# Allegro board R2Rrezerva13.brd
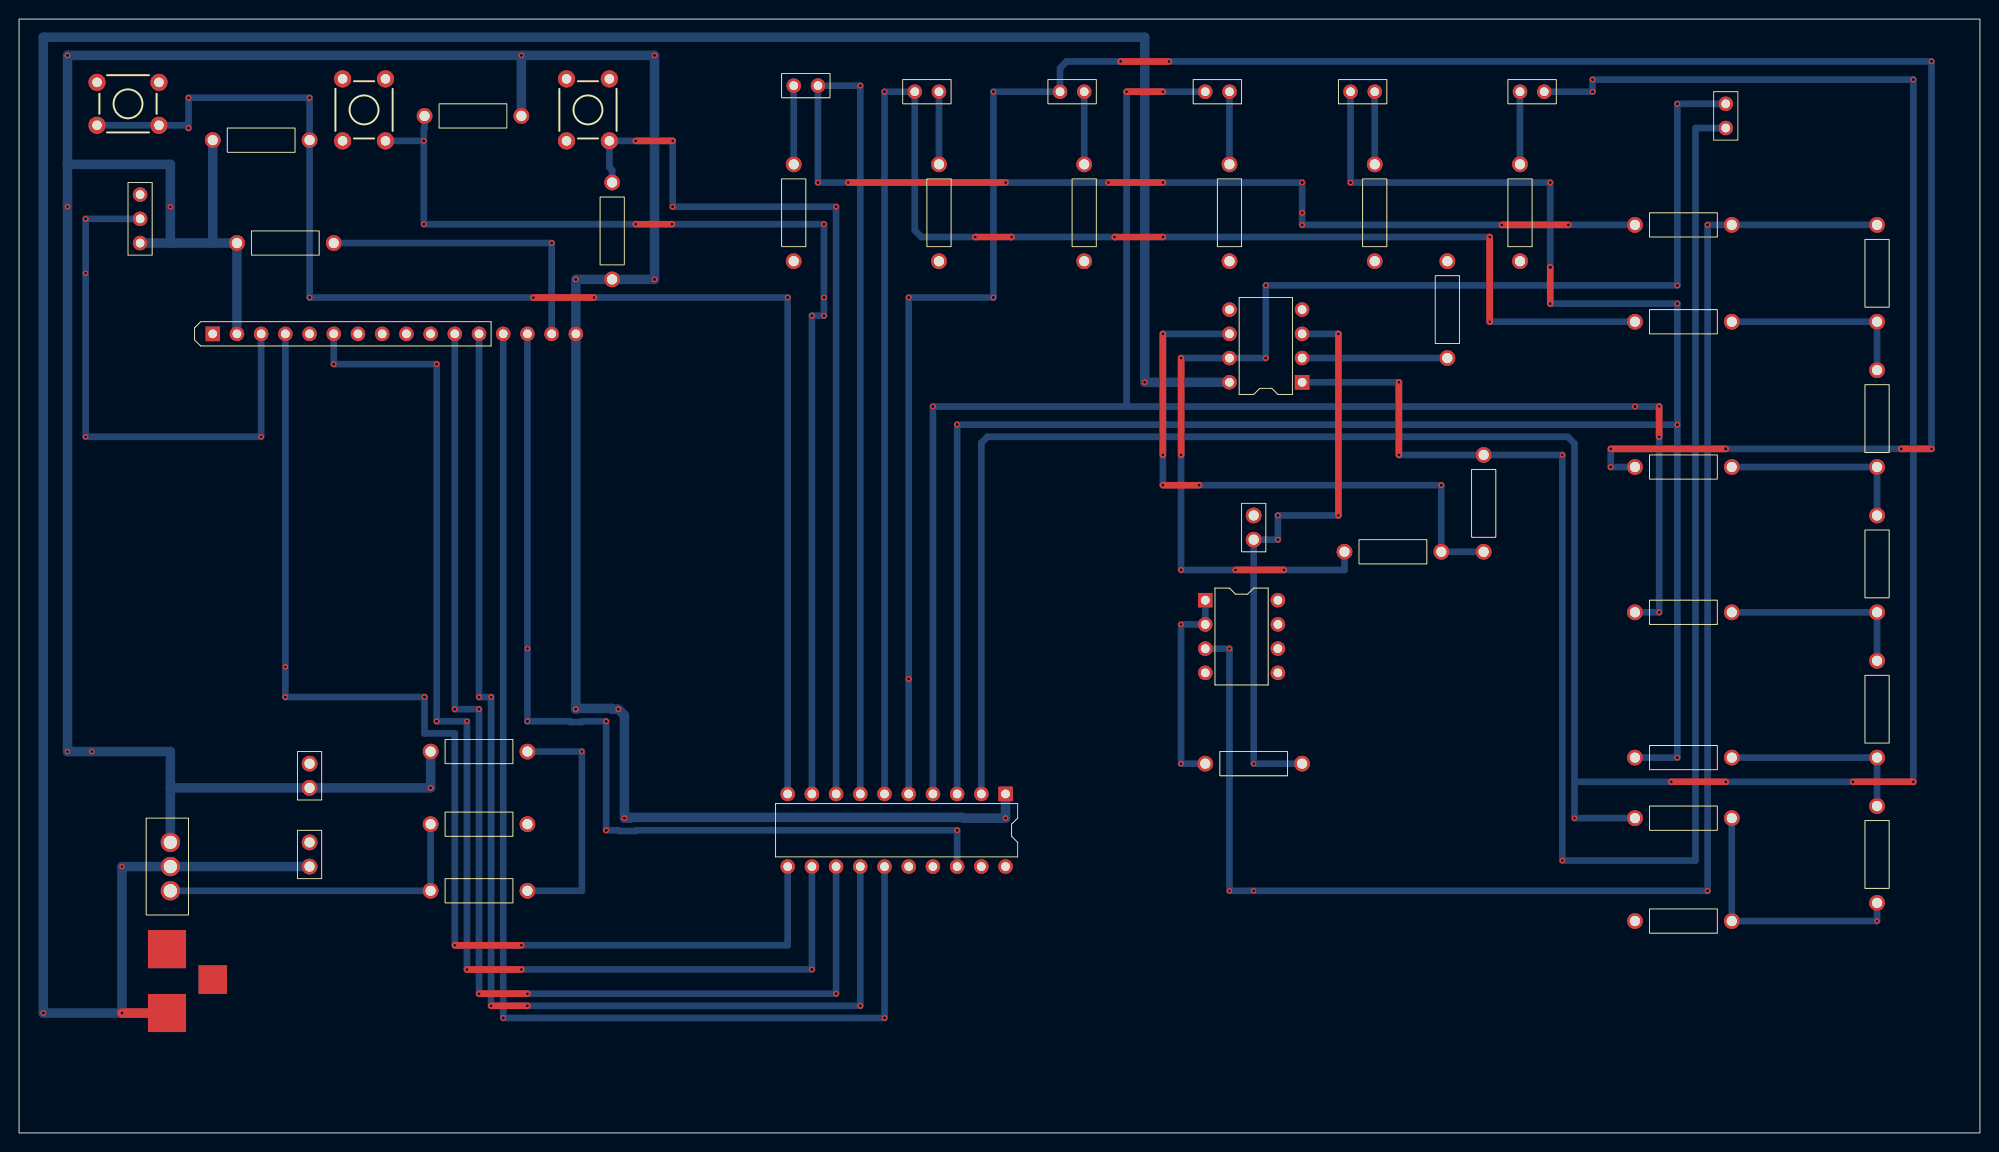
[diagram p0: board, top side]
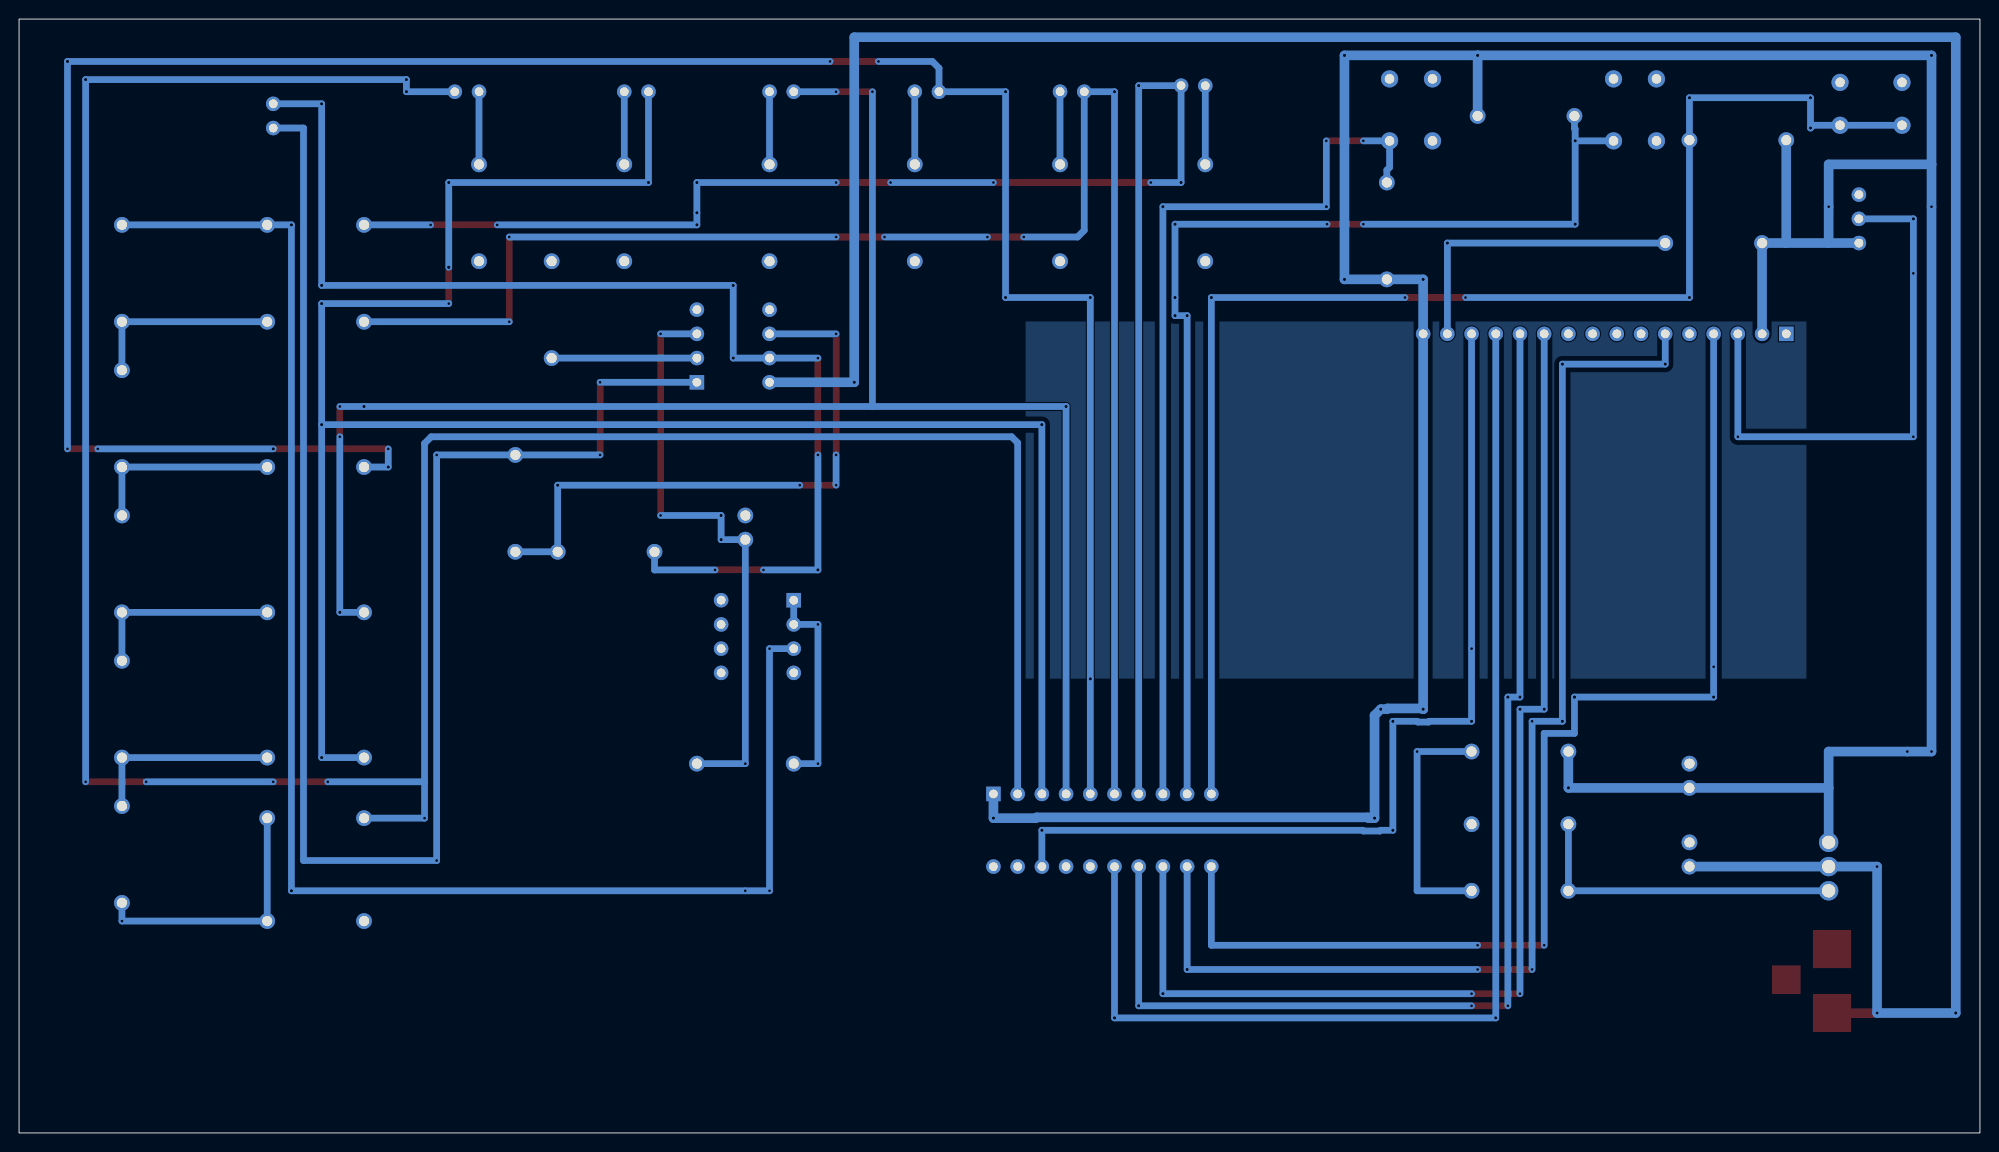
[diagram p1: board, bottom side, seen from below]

Outline 205.74 x 116.84 mm; copper layers: TOP, BOTTOM. Coordinates in mm from the lower left corner of the outline.
Outline path: rectangle 0,0 205.74,116.84

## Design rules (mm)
nets with their own width: min track width 0.7; nets N00328 N00336 N00340 N00355 N00395 N00470 N01662 N01669 N01683 N01690 N01717 N006340 N006500 N006660 N006820 N006980 N007140 N20855 N23488 N23661 N24189 N24193 N25824 N25853 N29134 N35057 N35516 N35592 N35638 N35656 N35674 N35692 N35721 N209781 SW1 SW2 SW3
nets with their own width: min track width 1; nets 0 9V V+ V- VCC

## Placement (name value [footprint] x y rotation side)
C3  10nf  [CAPCK05]  129.54 62.23 0 top
C4  10u  [CAPCK05]  30.48 30.48 180 top
C5  10u  [CAPCK05]  30.48 38.73 180 top
D1  MLED81  [JUMPER2]  83.82 109.85 180 top
D2  MLED81  [JUMPER2]  93.98 109.22 0 top
D3  MLED81  [JUMPER2]  109.22 109.22 0 top
D4  MLED81  [JUMPER2]  124.46 109.22 0 top
D5  MLED81  [JUMPER2]  139.7 109.22 0 top
D6  MLED81  [JUMPER2]  160.02 109.22 180 top
J1  Speaker  [JUMPER2]  179.07 105.41 90 top
J2  LCD 1602  [SIP16]  20.32 83.82 90 top
J3  CON3  [JACK_DC]  20.32 5.08 90 top
R2  1k  [RES400]  194.94 85.09 0 top
R3  1k  [RES400]  194.94 69.85 0 top
R4  1k  [RES400]  194.94 54.61 0 top
R5  1k  [RES400]  194.94 39.37 0 top
R6  1k  [RES400]  194.94 24.13 0 top
R7  2k  [RES400]  169.55 33.02 270 top
R8  2k  [RES400]  169.55 39.37 270 top
R9  2k  [RES400]  169.55 54.61 270 top
R10  2k  [RES400]  169.55 69.85 270 top
R11  2k  [RES400]  169.55 85.09 270 top
R12  2k  [RES400]  169.55 95.25 270 top
R13  2k  [RES400]  169.55 22.22 270 top
R14  470  [RES400]  157.48 91.44 0 top
R15  470  [RES400]  142.24 91.44 0 top
R16  470  [RES400]  127 91.44 0 top
R17  470  [RES400]  111.76 91.44 0 top
R18  470  [RES400]  96.52 91.44 0 top
R19  470  [RES400]  81.28 91.44 0 top
R20  10k  [RES400]  149.86 81.28 0 top
R22  10k  [RES400]  153.67 60.96 0 top
R23  1k  [RES400]  53.34 32.38 90 top
R24  470  [RES400]  53.34 40 90 top
R25  150  [RES400]  43.18 25.4 270 top
R26  33k  [RES400]  124.46 38.73 270 top
R28  10k  [RES400]  139.06 60.96 270 top
R29  1k  [JUMPER3]  12.7 98.42 270 top
R30  10k  [RES400]  30.48 104.14 90 top
R33  1k  [RES400]  22.86 93.34 270 top
R34  10k  [RES400]  42.55 106.68 270 top
R35  10k  [RES400]  62.23 99.69 180 top
SW7  SW_TC_SPST  [SW_SCHURTER_13019306L]  11.43 107.95 90 top
SW8  SW_TC_SPST  [SW_SCHURTER_13019306L]  36.19 107.31 180 top
SW9  SW_TC_SPST  [SW_SCHURTER_13019306L]  59.69 107.31 180 top
U1  MSP430G2553  [DIP20]  103.5 35.56 270 top
U7  LM317K  [TO220AB]  15.88 25.4 270 top
U9  LM358  [DIP8_3]  134.62 78.74 180 top
U10  LM358  [DIP8_3]  124.46 55.88 0 top

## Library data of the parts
C3-C5 = C: Tolerance: ***; User Part Number: ***
D1-D6 = MLED81: User Part Number: ***
J1 = CON2: User Part Number: ***
J2 = CON16: User Part Number: ***
J3 = CON3
R2-R20 R22-R26 R28 R30 R33-R35 = R: Tolerance: ***; User Part Number: ***
R29 = POT: User Part Number: ***
SW7-SW9 = SW_TC_SPST
U1 = MSP430G2553_4: Tolerance: ***; User Part Number: ***
U7 = LM317T
U9 = LM358: Tolerance: ***; User Part Number: ***
U10 = LM358_0: Tolerance: ***; User Part Number: ***

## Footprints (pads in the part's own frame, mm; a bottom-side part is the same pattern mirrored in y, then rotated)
CAPCK05
  round 1.651 hole 1.067: 1(0,0) 2(0,2.54)
DIP8_3
  rect 1.524x1.524 hole 0.914: 1(0,0)
  round 1.524 hole 0.914: 2(0,-2.54) 3(0,-5.08) 4(0,-7.62) 5(7.62,-7.62) 6(7.62,-5.08) 7(7.62,-2.54) 8(7.62,0)
DIP20
  rect 1.524x1.524 hole 0.914: 1(0,0)
  round 1.524 hole 0.914: 2(0,-2.54) 3(0,-5.08) 4(0,-7.62) 5(0,-10.16) 6(0,-12.7) 7(0,-15.24) 8(0,-17.78) 9(0,-20.32) 10(0,-22.86) 11(7.62,-22.86) 12(7.62,-20.32) 13(7.62,-17.78) 14(7.62,-15.24) 15(7.62,-12.7) 16(7.62,-10.16) 17(7.62,-7.62) 18(7.62,-5.08) 19(7.62,-2.54) 20(7.62,0)
JACK_DC
  rect 4x4 smd: 1(7.5,4.8) 2(14.2,4.8)
  rect 3x3 smd: 3(11,0)
JUMPER2
  round 1.524 hole 0.914: 1(0,0) 2(2.54,0)
JUMPER3
  round 1.524 hole 0.914: 1(0,0) 2(2.54,0) 3(5.08,0)
RES400
  round 1.651 hole 1.067: 1(0,0) 2(0,10.16)
SIP16
  rect 1.524x1.524 hole 0.914: 1(0,0)
  round 1.524 hole 0.914: 2(0,-2.54) 3(0,-5.08) 4(0,-7.62) 5(0,-10.16) 6(0,-12.7) 7(0,-15.24) 8(0,-17.78) 9(0,-20.32) 10(0,-22.86) 11(0,-25.4) 12(0,-27.94) 13(0,-30.48) 14(0,-33.02) 15(0,-35.56) 16(0,-38.1)
SW_SCHURTER_13019306L
  round 1.8 hole 1: 1(-2.25,-3.25) 2(-2.25,3.25) 3(2.25,3.25) 4(2.25,-3.25)
TO220AB
  round 2.032 hole 1.397: 1(0,0) 2(-2.54,0) 3(-5.08,0)

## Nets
9V: C4.2 J3.1 U7.2(IN) U9.8(V+)
VCC: C5.2 J2.2 J2.16 R24.2 R29.3(2) R30.2 R33.1 R34.2 R35.2 U1.1(DVCC) U7.3(OUT)
0: C3.2 C4.1 C5.1 J2.1 J2.5 J3.2 J3.3 R13.1 R14.1 R15.1 R16.1 R17.1 R18.1 R19.1 R20.2 R23.1 R29.1 SW7.3 SW8.3 SW9.3 U1.20(GROUND) U9.4(V-) U9.5(+)
SW1: R30.1 SW7.1 SW7.2 U1.10(P2_2)
SW2: R34.1 SW8.1 SW8.2 U1.9(P2_1)
SW3: R35.1 SW9.1 SW9.2 U1.8(P2_0/CS(B0))
V+: U10.8(V+)
V-: U10.4(V-)
N00328: R2.1 R3.2 R11.2
N00336: R4.1 R5.2 R9.2
N00340: R5.1 R6.2 R8.2
N00355: R2.2 R12.2 U10.3(+)
N00395: R3.1 R4.2 R10.2
N00470: R6.1 R7.2 R13.2
N01662: D5.1(A) R8.1 U1.3(P1_1/A1/RXD)
N01669: D4.1(A) R9.1 U1.4(P1_2/A2/TXD)
N01683: D2.1(A) R11.1 U1.6(P1_4/A4)
N01690: D1.1(A) R12.1 U1.7(P1_5/A5/SCK(B0))
N01717: D3.1(A) R10.1 U1.5(P1_3/A3/PUSH2)
N006340: D6.2(C) R14.2
N006500: D5.2(C) R15.2
N006660: D4.2(C) R16.2
N006820: D3.2(C) R17.2
N006980: D2.2(C) R18.2
N007140: D1.2(C) R19.2
N20855: R23.2 R25.1 U7.1(ADJ)
N23488: C3.1 R26.2 U9.3(+)
N23661: R26.1 U10.1(OUT) U10.2(-)
N24189: R20.1 U9.2(-)
N24193: J1.1 R22.2 U9.1(OUT)
N25824: R22.1 R28.2 U9.6(-)
N25853: J1.2 R28.1 U9.7(OUT)
N29134: D6.1(A) R7.1 U1.2(P1_0/A0/RED_LED)
N35057: J2.3 R29.2(T)
N35516: J2.4 U1.11(P2_3)
N35592: J2.6 U1.12(P2_4)
N35638: J2.11 U1.13(P2_5)
N35656: J2.12 U1.14(P1_6/A6/SCL/MISO(B0)/GREEN LED)
N35674: J2.13 U1.15(P1_7/A7/SDA/MOSE(B0))
N35692: J2.14 U1.18(P2_7/XOUT)
N35721: J2.15 R33.2
N209781: R24.1 R25.2

Pads without a net: J2 7 8 9 10; SW7 4; SW8 4; SW9 4; U1 16 17 19; U10 5 6 7

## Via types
v1: diameter 0.6, hole 0.3, TOP to BOTTOM, 240 vias

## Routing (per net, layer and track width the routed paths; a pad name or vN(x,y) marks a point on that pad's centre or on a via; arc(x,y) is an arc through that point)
9V: length 311
  TOP w1: J3.1 v1(10.8,12.58)
  BOTTOM w1: C4.2 U7.2 v1(10.8,27.94) v1(10.8,12.58) v1(2.54,12.58) 2.54,114.94 118.11,114.94 v1(118.11,78.74) U9.8
VCC: length 377.6
  BOTTOM w1: 15.88,36.19 15.88,40 v1(7.62,40) v1(5.08,40) v1(5.08,97.15) 5.08,101.6 ; 15.88,36.19 U7.3 ; 15.88,36.19 v1(43.18,36.19) R24.2 ; v1(52.71,113.03) v1(66.68,113.03) v1(66.68,89.53) R35.2 v1(58.42,89.53) J2.16 v1(58.42,44.45) 58.5,44.53 62.15,44.53 62.23,44.45 v1(62.87,44.45) 63.52,43.79 v1(63.52,33.02) 64.13,33.02 64.22,33.1 98.98,33.1 99.06,33.02 v1(103.5,33.02) U1.1 ; v1(52.71,113.03) R34.2 ; v1(52.71,113.03) v1(5.08,113.03) 5.08,101.6 ; 20.32,93.34 R33.1 J2.2 ; 20.32,93.34 15.88,93.34 ; 20.32,93.34 R30.2 ; R29.3 15.88,93.34 ; 15.88,93.34 v1(15.88,97.15) 15.88,101.6 5.08,101.6
SW1: length 148.8
  TOP w0.7: v1(53.98,87.63) v1(60.33,87.63)
  BOTTOM w0.7: v1(53.98,87.63) v1(30.48,87.63) R30.1 v1(30.48,108.58) v1(17.78,108.58) v1(17.78,105.41) 17.49,105.7 SW7.1 SW7.2 ; U1.10 v1(80.65,87.63) v1(60.33,87.63)
SW2: length 118.4
  TOP w0.7: v1(64.69,95.32) v1(68.5,95.32)
  BOTTOM w0.7: U1.9 v1(83.19,85.72) v1(84.46,85.72) v1(84.46,87.63) v1(84.46,95.32) v1(68.5,95.32) ; v1(42.47,104.06) 42.47,105.3 42.55,105.38 R34.1 ; v1(42.47,104.06) v1(42.47,95.32) v1(64.69,95.32) ; v1(42.47,104.06) SW8.2
SW3: length 96.8
  TOP w0.7: v1(64.69,104.06) v1(68.58,104.06)
  BOTTOM w0.7: v1(64.69,104.06) SW9.2 61.94,101.29 62.23,101 R35.1 ; v1(68.58,104.06) v1(68.58,97.15) v1(85.73,97.15) U1.8
N00328: length 20.3
  BOTTOM w0.7: R11.2 R2.1 R3.2
N00336: length 20.3
  BOTTOM w0.7: R9.2 R4.1 R5.2
N00340: length 20.3
  BOTTOM w0.7: R8.2 R5.1 R6.2
N00355: length 165.7
  BOTTOM w0.7: U10.3 v1(127,50.8) v1(127,25.4) v1(129.54,25.4) v1(177.17,25.4) v1(177.17,95.25) R12.2 R2.2
N00395: length 20.3
  BOTTOM w0.7: R10.2 R3.1 R4.2
N00470: length 27.9
  BOTTOM w0.7: R6.1 v1(194.94,22.22) R13.2 R7.2
N01662: length 222.9
  TOP w0.7: v1(160.66,90.8) v1(160.66,86.99)
  BOTTOM w0.7: v1(160.66,90.8) v1(160.66,99.69) v1(139.7,99.69) D5.1 ; v1(160.66,86.99) v1(173.99,86.99) v1(173.99,74.29) ; v1(173.99,74.29) v1(173.99,39.37) R8.1 ; v1(173.99,74.29) v1(98.43,74.29) U1.3
N01669: length 182.2
  TOP w0.7: v1(172.09,76.2) v1(172.09,73.02) ; v1(120.02,109.22) v1(116.21,109.22)
  BOTTOM w0.7: v1(116.21,109.22) 116.21,76.2 ; 116.21,76.2 v1(169.55,76.2) v1(172.09,76.2) ; 116.21,76.2 v1(95.88,76.2) U1.4 ; R9.1 v1(172.09,54.61) v1(172.09,73.02) ; D4.1 v1(120.02,109.22)
N01683: length 176.1
  TOP w0.7: v1(154.31,93.98) v1(154.31,85.09) ; v1(114.94,93.98) v1(120.02,93.98) ; v1(100.33,93.98) v1(104.14,93.98)
  BOTTOM w0.7: v1(120.02,93.98) v1(154.31,93.98) ; v1(104.14,93.98) v1(114.94,93.98) ; v1(154.31,85.09) R11.1 ; v1(100.33,93.98) 94.68,93.98 93.98,94.68 D2.1 v1(90.81,109.22) U1.6
N01690: length 179.1
  TOP w0.7: v1(114.3,99.69) v1(120.02,99.69) ; v1(87,99.69) v1(103.5,99.69) ; v1(155.58,95.25) v1(162.56,95.25)
  BOTTOM w0.7: v1(155.58,95.25) v1(134.62,95.25) v1(134.62,96.52) v1(134.62,99.69) v1(120.02,99.69) ; U1.7 v1(88.27,109.85) D1.1 v1(83.82,99.69) v1(87,99.69) ; v1(162.56,95.25) R12.1 ; v1(103.5,99.69) v1(114.3,99.69)
N01717: length 262.5
  TOP w0.7: v1(179.07,71.75) v1(167,71.75) ; v1(200.66,71.75) v1(197.49,71.75) ; v1(115.57,112.39) v1(120.65,112.39)
  BOTTOM w0.7: v1(167,71.75) v1(167,69.85) R10.1 ; v1(197.49,71.75) v1(179.07,71.75) ; U1.5 v1(93.35,47.62) v1(93.35,87.63) v1(102.24,87.63) v1(102.24,109.22) D3.1 109.22,111.69 109.92,112.39 v1(115.57,112.39) ; v1(200.66,71.75) v1(200.66,112.39) v1(120.65,112.39)
N006340: length 7.6
  BOTTOM w0.7: R14.2 D6.2
N006500: length 7.6
  BOTTOM w0.7: R15.2 D5.2
N006660: length 7.6
  BOTTOM w0.7: R16.2 D4.2
N006820: length 7.6
  BOTTOM w0.7: R17.2 D3.2
N006980: length 7.6
  BOTTOM w0.7: R18.2 D2.2
N007140: length 7.6
  BOTTOM w0.7: R19.2 81.28,109.22
N20855: length 34.3
  BOTTOM w0.7: R23.2 R25.1 U7.1
N23488: length 62.9
  TOP w0.7: v1(138.43,83.82) v1(138.43,64.77)
  BOTTOM w0.7: v1(138.43,64.77) v1(132.08,64.77) v1(132.08,62.23) v1(129.54,62.23) v1(129.54,38.73) R26.2 ; U9.3 v1(138.43,83.82)
N23661: length 22.2
  BOTTOM w0.7: U10.1 U10.2 v1(121.92,53.34) v1(121.92,38.73) R26.1
N24189: length 15.2
  BOTTOM w0.7: U9.2 R20.1
N24193: length 171.4
  TOP w0.7: v1(144.78,78.74) v1(144.78,71.12)
  BOTTOM w0.7: J1.1 175.9,105.41 175.9,28.57 v1(161.93,28.57) v1(161.93,71.12) R22.2 v1(144.78,71.12) ; U9.1 v1(144.78,78.74)
N25824: length 63.5
  TOP w0.7: v1(120.02,67.94) v1(123.83,67.94) ; v1(120.02,83.82) v1(120.02,71.12)
  BOTTOM w0.7: v1(123.83,67.94) v1(149.23,67.94) R28.2 R22.1 ; v1(120.02,71.12) v1(120.02,67.94) ; U9.6 v1(120.02,83.82)
N25853: length 125.1
  TOP w0.7: v1(127.63,59.05) v1(132.72,59.05) ; v1(121.92,81.28) v1(121.92,71.12)
  BOTTOM w0.7: v1(127.63,59.05) v1(121.92,59.05) v1(121.92,71.12) ; v1(121.92,81.28) U9.7 v1(130.81,81.28) v1(130.81,88.9) v1(173.99,88.9) v1(173.99,107.95) J1.2 ; v1(132.72,59.05) 139.06,59.05 R28.1
N29134: length 294.5
  TOP w0.7: v1(179.07,36.83) v1(173.36,36.83) ; v1(198.75,36.83) v1(192.41,36.83)
  BOTTOM w0.7: 163.19,36.83 163.19,72.32 162.5,73.02 101.6,73.02 100.97,72.39 U1.2 ; 163.19,36.83 v1(163.19,33.02) R7.1 ; 163.19,36.83 v1(173.36,36.83) ; v1(192.41,36.83) v1(179.07,36.83) ; v1(198.75,36.83) v1(198.75,110.49) v1(165.1,110.49) v1(165.1,109.22) D6.1
N35057: length 57.8
  BOTTOM w0.7: J2.3 v1(25.4,73.02) v1(6.99,73.02) v1(6.99,90.17) v1(6.99,95.88) R29.2
N35516: length 125.1
  TOP w0.7: v1(45.72,19.69) v1(52.71,19.69)
  BOTTOM w0.7: J2.4 v1(27.94,48.89) v1(27.94,45.72) v1(42.55,45.72) 42.55,41.91 45.72,41.91 v1(45.72,19.69) ; v1(52.71,19.69) 80.65,19.69 U1.11
N35592: length 127.6
  TOP w0.7: v1(52.71,17.14) v1(46.99,17.14)
  BOTTOM w0.7: U1.12 v1(83.19,17.14) v1(52.71,17.14) ; J2.6 v1(33.02,80.64) v1(43.81,80.64) v1(43.81,43.18) v1(46.99,43.18) v1(46.99,17.14)
N35638: length 122.6
  TOP w0.7: v1(53.34,14.6) v1(48.26,14.6)
  BOTTOM w0.7: v1(48.26,14.6) v1(48.26,44.45) v1(45.72,44.45) J2.11 ; v1(53.34,14.6) v1(85.73,14.6) U1.13
N35656: length 125.1
  TOP w0.7: v1(53.34,13.33) v1(49.53,13.33)
  BOTTOM w0.7: v1(53.34,13.33) v1(88.27,13.33) U1.14 ; v1(49.53,13.33) v1(49.53,45.72) v1(48.26,45.72) J2.12
N35674: length 127.6
  BOTTOM w0.7: U1.15 v1(90.81,12.06) v1(50.8,12.06) J2.13
N35692: length 101.1
  BOTTOM w0.7: U1.18 v1(98.43,31.75) 64.77,31.75 64.69,31.67 62.96,31.67 62.88,31.75 v1(61.6,31.75) v1(61.6,43.18) 59.06,43.18 58.98,43.1 57.86,43.1 57.78,43.18 v1(53.34,43.18) v1(53.34,50.8) J2.14
N35721: length 32.4
  BOTTOM w0.7: J2.15 v1(55.88,93.34) R33.2
N209781: length 26
  BOTTOM w0.7: R25.2 59.06,25.4 v1(59.06,40) R24.1

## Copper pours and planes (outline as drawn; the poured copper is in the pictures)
Net_17 on BOTTOM: 18.21,85.12 18.21,47.65 100.13,47.65 100.13,85.12
